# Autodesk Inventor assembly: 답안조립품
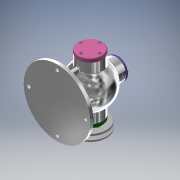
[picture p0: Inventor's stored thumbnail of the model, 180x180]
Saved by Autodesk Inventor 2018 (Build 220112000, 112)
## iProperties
Created: 2020-08
Part Number: 답안조립품
Material: 일반
Document SubType Name: Assembly
Designer: home
Author: home
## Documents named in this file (18)
- C:\Users\home\Desktop\700806V1044\답안조립품.iam
- C:\Users\home\Desktop\700806V1044\본체.ipt
- C:\Users\home\Desktop\700806V1044\앞커버.ipt
- C:\Users\home\Desktop\700806V1044\베어링 6202.ipt
- 베어링 6202.ipt
- C:\Users\home\Desktop\700806V1044\칼라.ipt
- C:\Users\home\Desktop\700806V1044\편심축.ipt
- C:\Users\home\Desktop\700806V1044\오일 실 15 30 7.ipt
- C:\Users\home\Desktop\700806V1044\뒤커버.ipt
- C:\Users\home\Desktop\700806V1044\멈춤링 35x1.6.ipt
- 멈춤링 35x1.6.ipt
- C:\Users\home\Desktop\700806V1044\멈춤링 15x1.ipt
- C:\Users\home\Desktop\700806V1044\상부커버.ipt
- C:\Users\home\Desktop\700806V1044\슬라이드.ipt
- C:\Users\home\Desktop\700806V1044\볼트 M4.ipt
- C:\Users\home\Desktop\700806V1044\V-벨트풀리.ipt
- C:\Users\home\Desktop\700806V1044\키 3x3x12.ipt
- C:\Users\home\Desktop\700806V1044\너트 M8.ipt
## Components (1 placed, 1 different names)
1. V-벨트풀리:1
